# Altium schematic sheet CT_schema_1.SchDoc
size 586 x 258 mm
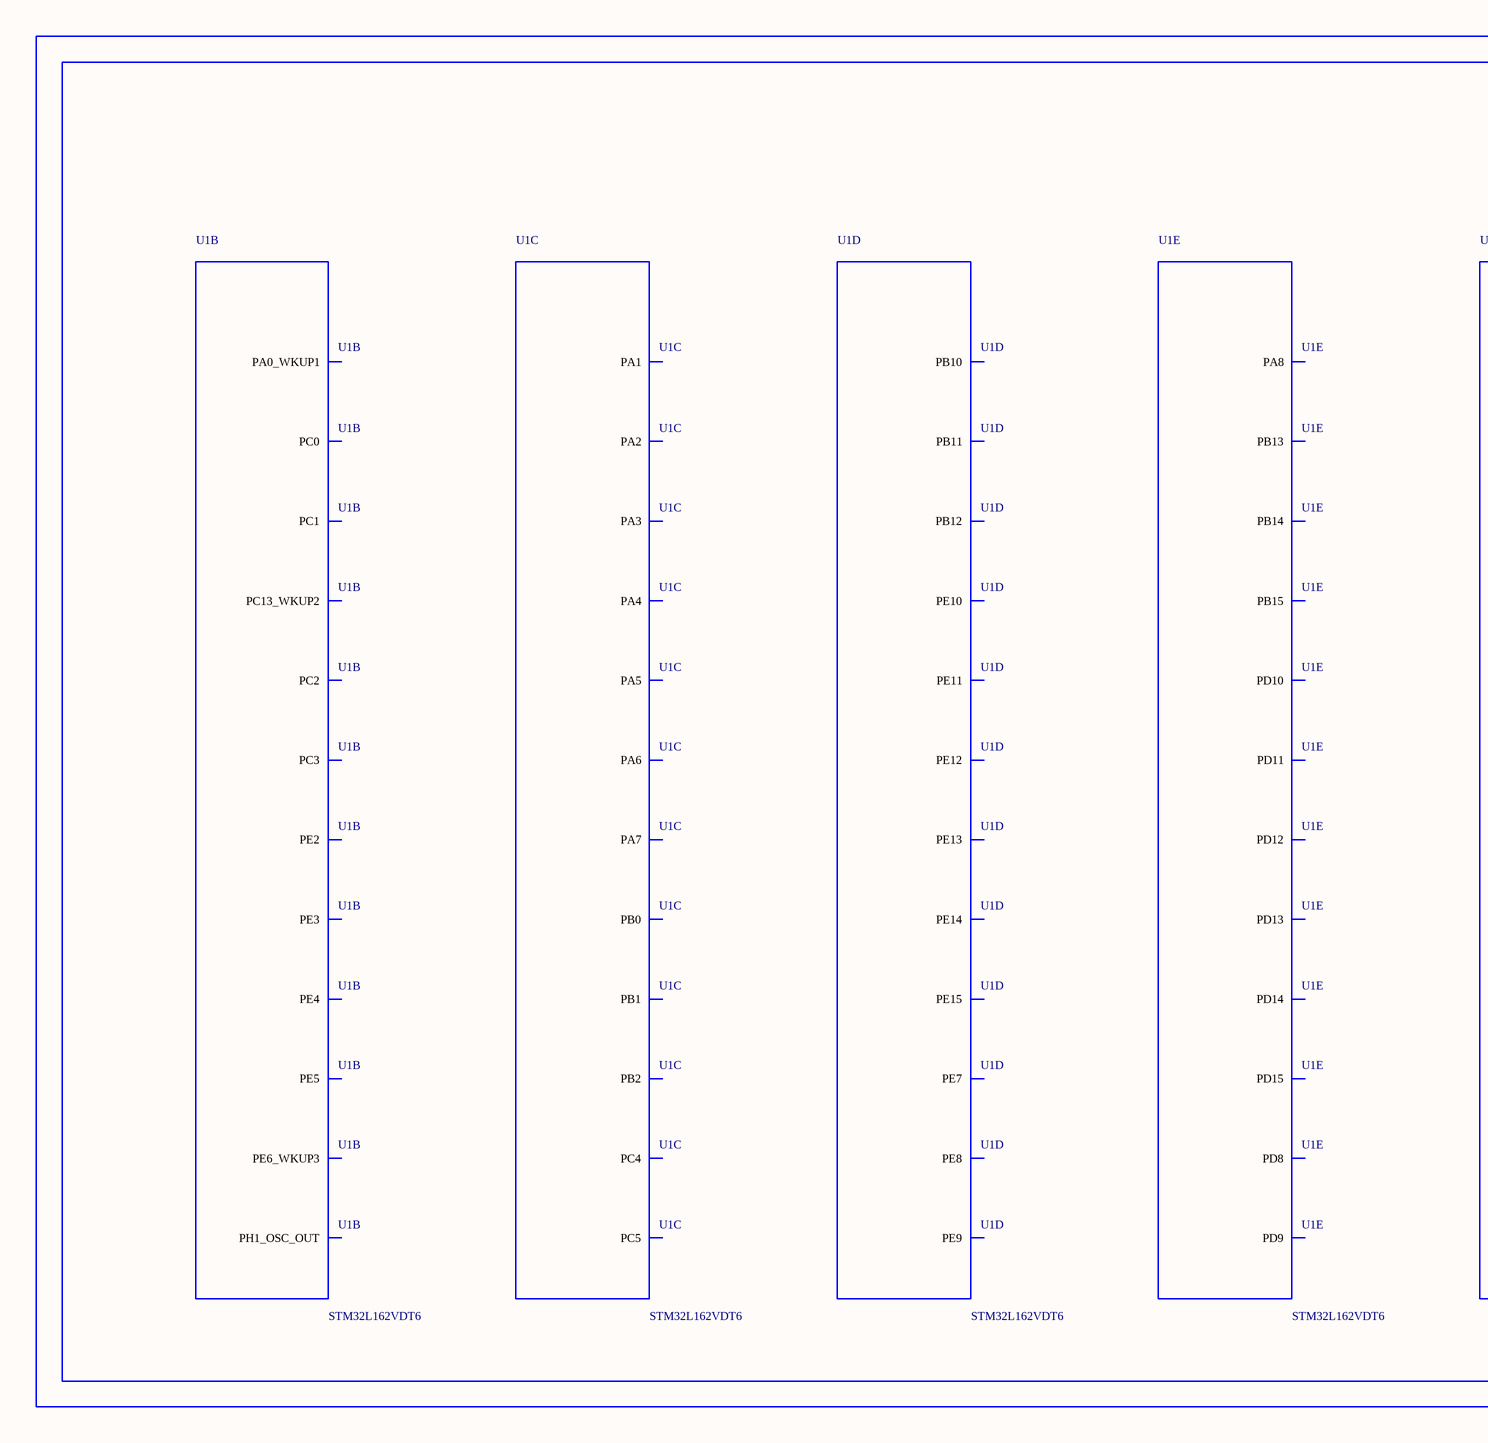
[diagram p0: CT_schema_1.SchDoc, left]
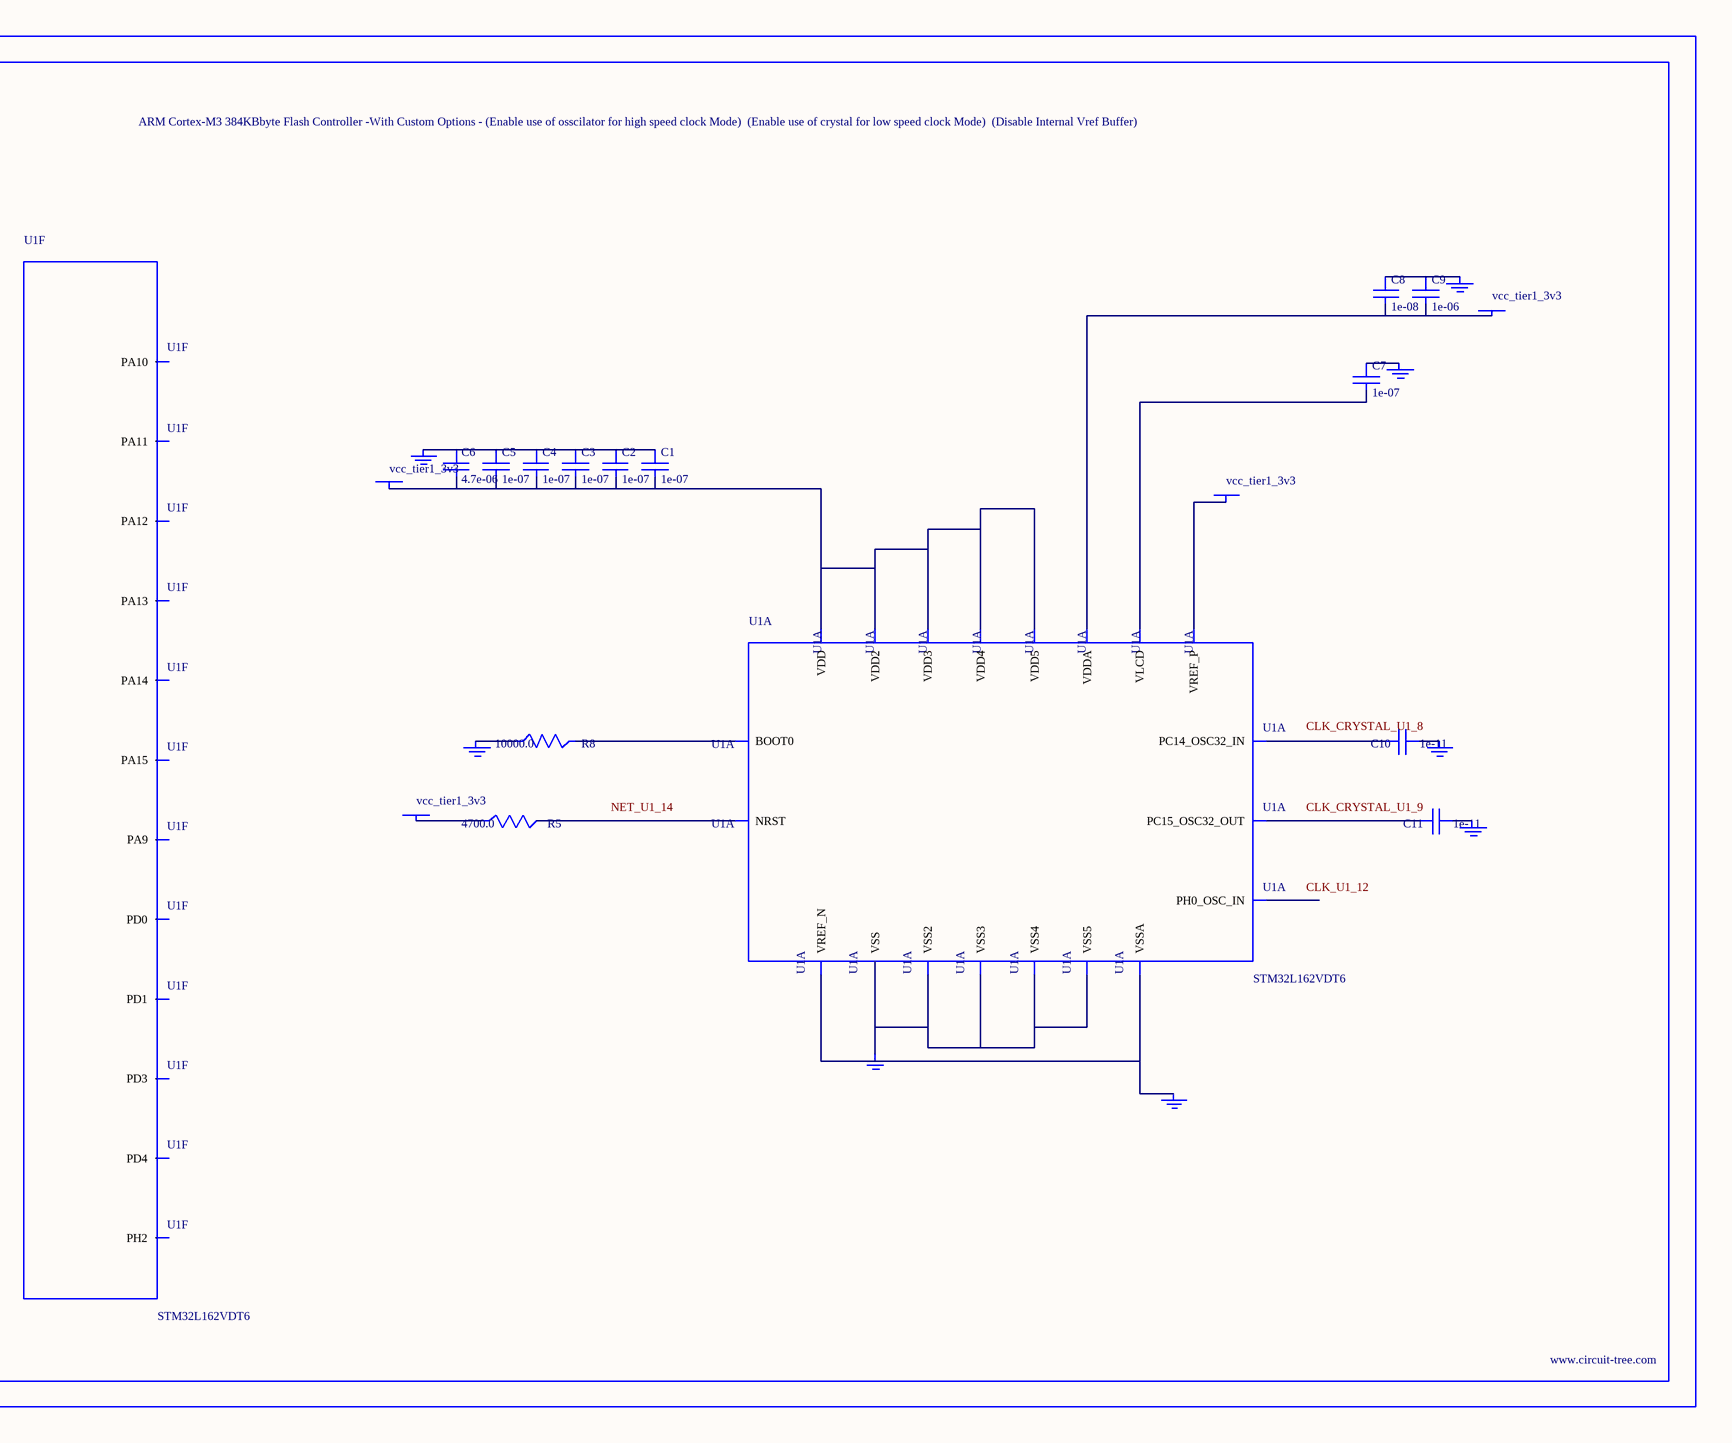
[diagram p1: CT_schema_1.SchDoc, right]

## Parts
BORDER0  (no value)
C1  1e-07  [C0603]
C2  1e-07  [C0603]
C3  1e-07  [C0603]
C4  1e-07  [C0603]
C5  1e-07  [C0603]
C6  4.7e-06  [C0603]
C7  1e-07  [C0603]
C8  1e-08  [C0603]
C9  1e-06  [C0603]
C10  1e-11  [C0402]
C11  1e-11  [C0402]
GND_INSTANCE_0_0  (no value)
GND_INSTANCE_0_1  (no value)
GND_INSTANCE_0_2  (no value)
GND_INSTANCE_0_3  (no value)
GND_INSTANCE_0_4  (no value)
GND_INSTANCE_0_5  (no value)
GND_INSTANCE_0_6  (no value)
GND_INSTANCE_0_7  (no value)
POWER_INSTANCE_0_0  vcc_tier1_3v3
POWER_INSTANCE_0_1  vcc_tier1_3v3
POWER_INSTANCE_0_2  vcc_tier1_3v3
POWER_INSTANCE_0_3  vcc_tier1_3v3
R5  4700.0  [R0603]
R8  10000.0  [R0603]
U1  STM32L162VDT6  [LQFP100]  (parts A,B,C,D,E,F of 8)

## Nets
NetC1_1: C1.1 C2.1 C3.1 C4.1 C5.1 C6.1 GND_INSTANCE_0_3.0(GND)
NetC1_2: C1.2 C2.2 C3.2 C4.2 C5.2 C6.2 POWER_INSTANCE_0_0.0(PWR) U1.11(VDD) U1.28(VDD2) U1.50(VDD3) U1.75(VDD4) U1.100(VDD5)
NetC7_1: C7.1 GND_INSTANCE_0_0.0(GND)
NetC7_2: C7.2 U1.6(VLCD)
NetC8_1: C8.1 C9.1 GND_INSTANCE_0_5.0(GND)
NetC8_2: C8.2 C9.2 POWER_INSTANCE_0_2.0(PWR) U1.22(VDDA)
NetC10_1: C10.1 GND_INSTANCE_0_1.0(GND)
NetC10_2: C10.2 U1.8(PC14_OSC32_IN)
NetC11_1: C11.1 GND_INSTANCE_0_2.0(GND)
NetC11_2: C11.2 U1.9(PC15_OSC32_OUT)
NetGND_INSTANCE_0_4_0: GND_INSTANCE_0_4.0(GND) U1.19(VSSA) U1.20(VREF_N)
NetGND_INSTANCE_0_6_0: GND_INSTANCE_0_6.0(GND) R8.1
NetGND_INSTANCE_0_7_0: GND_INSTANCE_0_7.0(GND) U1.10(VSS) U1.27(VSS2) U1.49(VSS3) U1.74(VSS4) U1.99(VSS5)
NetPOWER_INSTANCE_0_1_0: POWER_INSTANCE_0_1.0(PWR) U1.21(VREF_P)
NetPOWER_INSTANCE_0_3_0: POWER_INSTANCE_0_3.0(PWR) R5.1
NetR5_2: R5.2 U1.14(NRST)
NetR8_2: R8.2 U1.94(BOOT0)

Not connected (* = marked no-connect by the designer): U1 1(PE2) 2(PE3) 3(PE4) 4(PE5) 5(PE6_WKUP3) 7(PC13_WKUP2) 12(PH0_OSC_IN) 13(PH1_OSC_OUT) 15(PC0) 16(PC1) 17(PC2) 18(PC3) 23(PA0_WKUP1) 24(PA1) 25(PA2) 26(PA3) 29(PA4) 30(PA5) 31(PA6) 32(PA7) 33(PC4) 34(PC5) 35(PB0) 36(PB1) 37(PB2) 38(PE7) 39(PE8) 40(PE9) 41(PE10) 42(PE11) 43(PE12) 44(PE13) 45(PE14) 46(PE15) 47(PB10) 48(PB11) 51(PB12) 52(PB13) 53(PB14) 54(PB15) 55(PD8) 56(PD9) 57(PD10) 58(PD11) 59(PD12) 60(PD13) 61(PD14) 62(PD15) 67(PA8) 68(PA9) 69(PA10) 70(PA11) 71(PA12) 72(PA13) 73(PH2) 76(PA14) 77(PA15) 81(PD0) 82(PD1) 84(PD3) 85(PD4)

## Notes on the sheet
- Labels drawn without touching a wire or pin: CLK_CRYSTAL_U1_8, CLK_CRYSTAL_U1_9, CLK_U1_12, NET_U1_14

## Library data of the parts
BORDER0 = BORDER_PAGE0
C1-C5 C7 = 06035C104K4Z2A
C6 = GRM188R6YA475KE15D
C8 = 06035C103K4Z2A
C9 = C0603C105K3RACTU
C10 C11 = C0402C100K3GACTU
GND_INSTANCE_0_0-GND_INSTANCE_0_7 = GND
POWER_INSTANCE_0_0-POWER_INSTANCE_0_3 = PWR
R5 = RC0603JR-074K7L
R8 = RC0603JR-0710KL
